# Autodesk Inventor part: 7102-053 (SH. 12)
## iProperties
Created: 2006-07
Part Number: 7102-053 (SH. 12)
Material: Stainless Steel, 316
Description: GATE VALVE FLANGE
Document SubType Name: Modeling
Designer: Henneborn
Manufacturer: Standard
Standards Organization: Custom
Density: 7.9 g/cm^3
Rohmasse: 7,2" O.D.  x 0,5" made of sheet
Author: vm
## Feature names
1. Extrusion1
2. Extrusion2
3. Chamfer1
4. Chamfer2
5. Hole1
6. Circular Pattern1
